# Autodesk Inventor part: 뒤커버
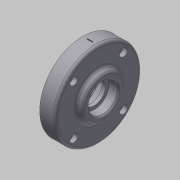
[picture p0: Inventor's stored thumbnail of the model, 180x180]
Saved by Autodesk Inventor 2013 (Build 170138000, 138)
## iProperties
Company: 한국ATC센터
Created: 2015-12
Part Number: 뒤커버
Document SubType Name: Modeling
Designer: mdu
Density: 2.71 g/cm^3
Mass: 97.9606 g
Surface Area: 115.544 cm^2
Volume: 36.1478 cm^3
Material: 알루미늄-6061
Author: mdu
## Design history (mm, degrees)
sketch "스케치1"
  geometry: L1 (-10.5, 0)-(10.5, 0); L2 (10.5, 0)-(10.5, 22.5); L3 (10.5, 22.5)-(5.5, 22.5); L4 (5.5, 22.5)-(5.5, 32.5); L5 (5.5, 32.5)-(-6.5, 32.5); L6 (-6.5, 32.5)-(-6.5, 17.5); L7 (-6.5, 17.5)-(-10.5, 15.191); L8 (-10.5, 15.191)-(-10.5, 0); 2 further points
  constraints: 16 end point, 3 parallel, 3 perpendicular, 1 coincident, 1 horizontal, 1 midpoint
  dimensions: "d0" = 21 distance of L1.start L1.end; "d1" = 65 diameter of L5 L1; "d2" = 45 diameter of L3 L1; "d3" = 35 diameter of L6.end L1; "d4" = 120 deg angle of L7 L6; "d5" = 12 distance of L4.end L5.end; "d6" = 5 distance of L2.end L3.end
revolve "회전1" sketch "스케치1" stored, may be unused: angle "d7" = 90 deg
sketch "스케치2"
  geometry: L1 (0, 0)-(32.5, 0); L2 (0, 0)-(18.738, 18.738); 1 further point
  constraints: 4 end point, 1 horizontal, 1 horizontal alignment, 1 other
  dimensions: "d8" = 45 deg angle of L1 L2; "d9" = 26.5 distance of L1.start L2.end
hole "구멍1" sketch "스케치2" at (18.738, 18.738) diameter "d10" = 3.4; stored, may be unused: countersink angle "d14" = 90 deg, drill point angle "d16" = 118 deg; dims "d11" = 6, "d12" = 6, "d13" = 3.3, "d15" = 8
fillet "모깎기1" dims "d20" = 2
hole "구멍2" diameter "d23" = 15; stored, may be unused: countersink angle "d27" = 90 deg, drill point angle "d29" = 0 deg; dims "d21" = 10, "d22" = 10, "d24" = 6, "d25" = 35, "d26" = 11, "d28" = 14
chamfer "모따기1" distance "d39" = 1; stored, may be unused: second distance "d40" = 2, angle "d41" = 45 deg
fillet "모깎기2" dims "d42" = 0.3
hole "구멍4" diameter "d46" = 17; stored, may be unused: countersink angle "d50" = 90 deg, drill point angle "d52" = 118 deg; dims "d44" = 10, "d45" = 10, "d47" = 6, "d48" = 22, "d49" = 7.3, "d51" = 8
chamfer "모따기2" distance "d53" = 1; stored, may be unused: second distance "d54" = 2, angle "d55" = 45 deg
fillet "모깎기3" dims "d56" = 0.3
node "작업 평면1"
sketch "스케치3"
  geometry: 2 further points
  constraints: 1 coincident, 1 other
feature "엠보싱1" sketch "스케치3" dims "d0" = 21, "d1" = 65, "d2" = 45, "d3" = 35, "d4" = 120 deg, "d5" = 12, "d6" = 5, "d58" = 0.3, "d59" = 0
fillet "모깎기4" dims "d60" = 0.2
fillet "모깎기5" dims "d61" = 0.1
node "솔리드1"
pattern_circular "원형 패턴1" dims angle "d18" = 360 deg
